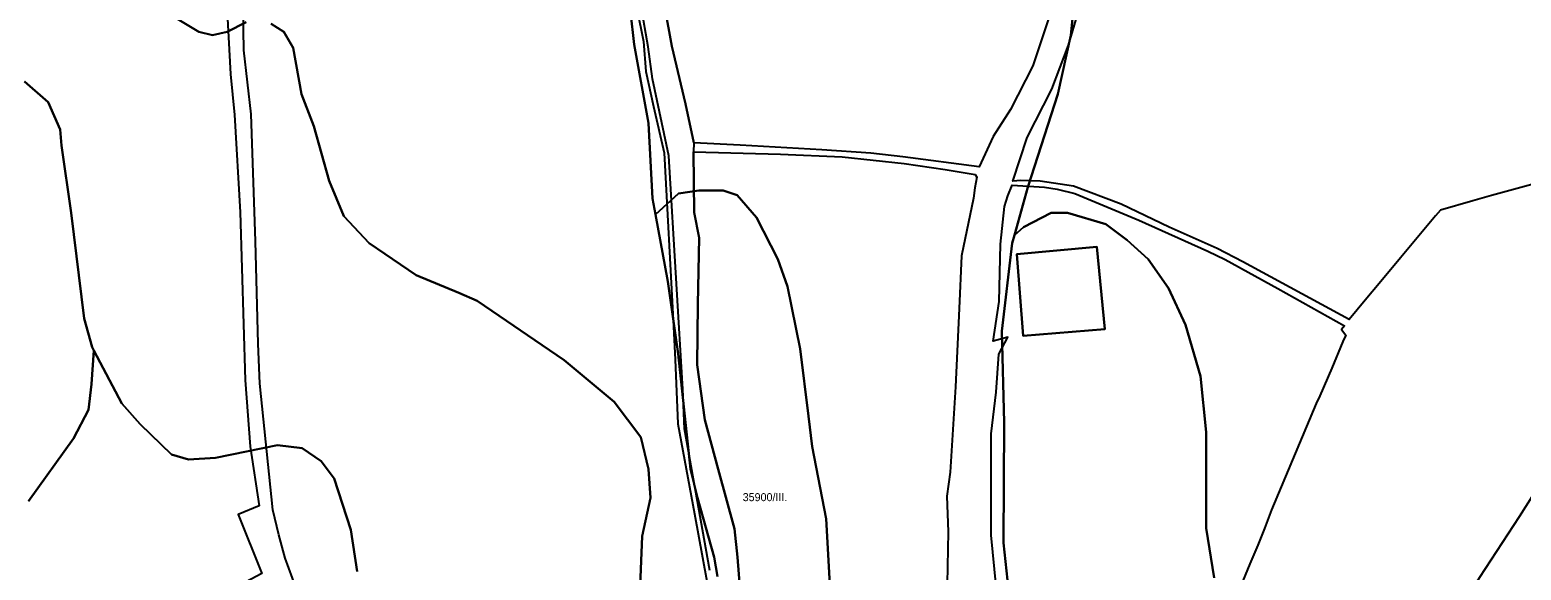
# Model space of a CAD drawing. Extents: x -532083 to -529270, y -1180561 to -1176456.
# Drawn here: x -531139 to -530208, y -1177679 to -1177342 of the extents above; entities that cross this region are included whole.
import ezdxf

# ---------------------------------------------------------------- set-up
doc = ezdxf.new("R2010")
doc.units = 0
for name, color, linetype in [('95560013', 7, 'Continuous'), ('95610013', 7, 'Continuous'), ('95660013', 7, 'Continuous')]:
    doc.layers.add(name, color=color, linetype=linetype)

msp = doc.modelspace()

# ---------------------------------------------------------------- linework, layer by layer
at = {"layer": '95560013'}
for points in [[(-530972.9683, -1177690.35345), (-530979.8183, -1177671.66545), (-530983.9283, -1177657.09845), (-530987.4903, -1177641.43345), (-530995.7103, -1177562.55645), (-530996.6723, -1177537.90445), (-530998.3133, -1177473.68045), (-531001.1283, -1177394.47345), (-531005.7623, -1177354.41745), (-531006.6203, -1177303.21945)], [(-530497.9153, -1177319.13345), (-530512.7543, -1177364.23845), (-530526.8243, -1177391.53445), (-530537.6733, -1177408.35145), (-530546.3023, -1177427.39445), (-530594.1343, -1177420.96445), (-530614.1053, -1177418.73845), (-530644.6773, -1177416.76045), (-530695.5913, -1177413.83345), (-530724.5473, -1177412.26945), (-530729.8643, -1177388.03045), (-530738.3213, -1177351.91345), (-530742.6713, -1177327.91645)], [(-530163.0193, -1177427.87145), (-530226.4153, -1177445.25745), (-530238.0503, -1177448.59145), (-530258.2323, -1177454.30845), (-530261.3193, -1177457.88045), (-530283.1633, -1177484.07945), (-530295.5103, -1177498.84545), (-530305.2453, -1177510.51545), (-530315.2923, -1177522.64845), (-530381.6713, -1177486.67145), (-530397.7303, -1177478.34845), (-530427.7073, -1177464.92445), (-530457.6853, -1177450.69545), (-530487.3953, -1177439.41945), (-530508.2723, -1177436.19745), (-530520.3163, -1177435.92845), (-530525.2543, -1177436.31745), (-530516.3373, -1177408.95945), (-530500.8653, -1177378.70845), (-530490.6373, -1177351.35145), (-530481.9833, -1177322.15245)], [(-531016.1163, -1177330.85845), (-531013.9583, -1177369.33145), (-531011.5613, -1177394.82245), (-531007.9653, -1177455.65945), (-531004.8483, -1177560.50445), (-531001.7323, -1177601.86645), (-530996.1843, -1177639.00245), (-531009.2363, -1177644.47345), (-530994.4313, -1177681.21145), (-531066.9013, -1177719.70745), (-531091.9053, -1177732.76545), (-531118.2913, -1177744.82245), (-531146.1423, -1177755.99745)], [(-530760.1993, -1177328.34445), (-530756.1083, -1177349.07945), (-530754.6013, -1177367.86945), (-530749.8703, -1177389.65445), (-530743.1753, -1177418.50645), (-530737.4993, -1177523.03345), (-530736.1873, -1177547.59845), (-530734.6563, -1177587.73645), (-530724.2453, -1177644.04445), (-530711.3873, -1177713.36945)], [(-530714.6403, -1177679.39445), (-530730.3473, -1177590.91845), (-530731.5553, -1177566.19345), (-530735.4223, -1177500.26045), (-530740.2553, -1177420.51045), (-530750.4043, -1177372.27445), (-530753.0623, -1177352.39845), (-530757.4123, -1177327.43145)], [(-530742.6713, -1177327.91645), (-530738.3213, -1177351.91345), (-530729.8643, -1177388.03045), (-530724.5473, -1177412.26945), (-530724.7193, -1177417.95145), (-530724.4793, -1177455.74945), (-530721.3593, -1177471.63845), (-530722.0793, -1177513.04645), (-530722.6183, -1177551.01945), (-530717.7763, -1177585.23745), (-530709.4133, -1177616.14445), (-530699.2893, -1177653.23245), (-530697.4183, -1177670.94245), (-530695.2093, -1177697.53345)], [(-530695.2093, -1177697.53345), (-530697.4183, -1177670.94245), (-530699.2893, -1177653.23245), (-530709.4133, -1177616.14445), (-530717.7763, -1177585.23745), (-530722.6183, -1177551.01945), (-530722.0793, -1177513.04645), (-530721.3593, -1177471.63845), (-530724.4793, -1177455.74945), (-530724.7193, -1177417.95145), (-530670.5343, -1177419.41845), (-530631.8653, -1177420.97045), (-530593.1953, -1177425.31445), (-530567.5193, -1177429.03845), (-530548.9583, -1177432.14145), (-530547.7813, -1177433.82545), (-530549.0143, -1177440.50245), (-530549.8333, -1177446.93445), (-530557.3753, -1177482.82145), (-530558.9533, -1177515.79945), (-530561.0733, -1177564.70345), (-530564.5173, -1177617.85945), (-530566.6373, -1177633.00845), (-530565.7593, -1177655.31045), (-530566.2513, -1177687.61045)], [(-530534.7493, -1177699.73945), (-530538.8693, -1177657.20545), (-530538.9023, -1177594.00945), (-530535.6643, -1177568.02745), (-530534.0453, -1177544.21145), (-530528.3793, -1177533.65645), (-530537.6503, -1177536.16645), (-530533.7823, -1177511.33645), (-530533.0093, -1177475.64445), (-530530.5233, -1177452.12645), (-530528.5503, -1177445.44845), (-530525.8383, -1177438.77145), (-530505.5953, -1177439.95645), (-530497.5663, -1177441.29845), (-530486.5923, -1177443.98345), (-530446.7113, -1177460.62945), (-530403.6183, -1177479.95945), (-530392.6443, -1177485.06045), (-530359.7233, -1177503.31745), (-530318.2363, -1177526.67545), (-530320.0873, -1177528.96545), (-530317.4173, -1177532.31245), (-530319.0863, -1177536.32945), (-530326.0943, -1177553.06645), (-530333.5213, -1177570.34045), (-530335.8553, -1177575.02345), (-530363.7173, -1177641.40045), (-530368.1183, -1177653.17445), (-530372.2263, -1177663.47645), (-530377.2153, -1177675.24945), (-530381.6163, -1177685.84645)], [(-530202.5013, -1177886.43345), (-530280.6013, -1177914.22245), (-530299.8523, -1177901.09045), (-530283.3193, -1177875.02245), (-530332.0333, -1177842.15945), (-530288.9793, -1177773.56145), (-530233.5283, -1177683.50645), (-530208.8843, -1177645.54245), (-530157.0203, -1177563.79845)]]:
    msp.add_lwpolyline(points, dxfattribs=at)
msp.add_lwpolyline([(-530518.9233, -1177532.82145), (-530467.9253, -1177528.59545), (-530472.8033, -1177477.21845), (-530522.9143, -1177481.88945)], close=True, dxfattribs=at)
at = {"layer": '95610013'}
msp.add_lwpolyline([(-530467.9253, -1177528.59545), (-530518.9233, -1177532.82145), (-530522.9143, -1177481.88945), (-530472.8033, -1177477.21845)], close=True, dxfattribs=at)
at = {"layer": '95660013'}
for points in [[(-530485.1253, -1177306.00045), (-530489.1253, -1177345.00045), (-530497.3123, -1177382.00045), (-530515.8753, -1177440.00045), (-530524.3753, -1177470.00045), (-530525.8123, -1177475.00045), (-530532.1253, -1177530.00045), (-530530.8123, -1177587.00045), (-530531.1253, -1177662.00045), (-530527.5003, -1177697.00045)], [(-530399.6253, -1177684.00045), (-530404.6253, -1177653.00045), (-530404.6253, -1177593.00045), (-530408.1873, -1177558.00045), (-530417.3753, -1177526.00045), (-530428.1253, -1177503.00045), (-530440.6873, -1177485.00045), (-530453.8753, -1177473.00045), (-530467.1873, -1177463.00045), (-530491.1253, -1177456.00045), (-530501.3123, -1177456.00045), (-530518.6253, -1177465.00045), (-530524.3753, -1177470.00045), (-530515.8753, -1177440.00045), (-530497.3123, -1177382.00045), (-530489.1253, -1177345.00045), (-530485.1253, -1177306.00045)], [(-530766.3753, -1177310.00045), (-530761.8753, -1177351.00045), (-530753.0003, -1177400.00045), (-530750.3753, -1177447.00045), (-530748.5003, -1177457.00045), (-530740.8753, -1177499.00045), (-530734.3753, -1177544.00045), (-530726.6253, -1177616.00045), (-530722.3123, -1177634.00045), (-530711.8753, -1177671.00045), (-530709.8753, -1177683.00045)], [(-530639.6253, -1177688.00045), (-530641.8753, -1177647.00045), (-530650.6253, -1177602.00045), (-530652.8753, -1177583.00045), (-530658.1873, -1177541.00045), (-530666.1873, -1177502.00045), (-530672.1873, -1177485.00045), (-530685.5003, -1177459.00045), (-530697.5003, -1177445.00045), (-530706.1873, -1177442.00045), (-530721.5003, -1177442.00045), (-530734.1253, -1177444.00045), (-530748.5003, -1177457.00045), (-530750.3753, -1177447.00045), (-530753.0003, -1177400.00045), (-530761.8753, -1177351.00045), (-530766.3753, -1177310.00045)], [(-531004.3123, -1177337.00045), (-531016.1253, -1177343.00045), (-531025.3123, -1177345.00045), (-531033.8123, -1177343.00045), (-531050.3753, -1177333.00045)], [(-531050.3753, -1177333.00045), (-531033.8123, -1177343.00045), (-531025.3123, -1177345.00045), (-531016.1253, -1177343.00045), (-531004.3123, -1177337.00045)], [(-530758.3123, -1177694.00045), (-530756.8753, -1177658.00045), (-530751.6873, -1177634.00045), (-530753.0003, -1177616.00045), (-530757.6253, -1177596.00045), (-530774.3123, -1177574.00045), (-530805.6253, -1177548.00045), (-530859.8753, -1177511.00045), (-530871.3123, -1177506.00045), (-530898.1253, -1177495.00045), (-530927.5003, -1177475.00045), (-530943.1873, -1177458.00045), (-530952.3753, -1177436.00045), (-530961.8753, -1177402.00045), (-530969.6873, -1177382.00045), (-530974.8753, -1177353.00045), (-530980.8123, -1177343.00045), (-530988.6253, -1177338.00045)], [(-530988.6253, -1177338.00045), (-530980.8123, -1177343.00045), (-530974.8753, -1177353.00045), (-530969.6873, -1177382.00045), (-530961.8753, -1177402.00045), (-530952.3753, -1177436.00045), (-530943.1873, -1177458.00045), (-530927.5003, -1177475.00045), (-530898.1253, -1177495.00045), (-530871.3123, -1177506.00045), (-530859.8753, -1177511.00045), (-530805.6253, -1177548.00045), (-530774.3123, -1177574.00045), (-530757.6253, -1177596.00045), (-530753.0003, -1177616.00045), (-530751.6873, -1177634.00045), (-530756.8753, -1177658.00045), (-530758.3123, -1177694.00045)], [(-531142.6253, -1177374.00045), (-531127.8753, -1177387.00045), (-531120.5003, -1177404.00045), (-531119.5003, -1177414.00045), (-531113.5003, -1177456.00045), (-531105.5003, -1177522.00045), (-531100.3753, -1177540.00045), (-531099.3123, -1177542.00045), (-531100.8123, -1177563.00045), (-531102.8123, -1177579.00045), (-531112.1873, -1177597.00045), (-531140.3123, -1177636.00045)], [(-530934.8123, -1177680.00045), (-530938.8753, -1177654.00045), (-530949.3123, -1177622.00045), (-530957.3123, -1177611.00045), (-530969.3123, -1177603.00045), (-530984.6873, -1177601.00045), (-531023.5003, -1177609.00045), (-531040.3123, -1177610.00045), (-531050.8753, -1177607.00045), (-531070.3753, -1177588.00045), (-531081.8123, -1177575.00045), (-531099.3123, -1177542.00045), (-531100.3753, -1177540.00045), (-531105.5003, -1177522.00045), (-531113.5003, -1177456.00045), (-531119.5003, -1177414.00045), (-531120.5003, -1177404.00045), (-531127.8753, -1177387.00045), (-531142.6253, -1177374.00045)], [(-530709.8753, -1177683.00045), (-530711.8753, -1177671.00045), (-530722.3123, -1177634.00045), (-530726.6253, -1177616.00045), (-530734.3753, -1177544.00045), (-530740.8753, -1177499.00045), (-530748.5003, -1177457.00045), (-530734.1253, -1177444.00045), (-530721.5003, -1177442.00045), (-530706.1873, -1177442.00045), (-530697.5003, -1177445.00045), (-530685.5003, -1177459.00045), (-530672.1873, -1177485.00045), (-530666.1873, -1177502.00045), (-530658.1873, -1177541.00045), (-530652.8753, -1177583.00045), (-530650.6253, -1177602.00045), (-530641.8753, -1177647.00045), (-530639.6253, -1177688.00045)], [(-530527.5003, -1177697.00045), (-530531.1253, -1177662.00045), (-530530.8123, -1177587.00045), (-530532.1253, -1177530.00045), (-530525.8123, -1177475.00045), (-530524.3753, -1177470.00045), (-530518.6253, -1177465.00045), (-530501.3123, -1177456.00045), (-530491.1253, -1177456.00045), (-530467.1873, -1177463.00045), (-530453.8753, -1177473.00045), (-530440.6873, -1177485.00045), (-530428.1253, -1177503.00045), (-530417.3753, -1177526.00045), (-530408.1873, -1177558.00045), (-530404.6253, -1177593.00045), (-530404.6253, -1177653.00045), (-530399.6253, -1177684.00045)], [(-531140.3123, -1177636.00045), (-531112.1873, -1177597.00045), (-531102.8123, -1177579.00045), (-531100.8123, -1177563.00045), (-531099.3123, -1177542.00045), (-531081.8123, -1177575.00045), (-531070.3753, -1177588.00045), (-531050.8753, -1177607.00045), (-531040.3123, -1177610.00045), (-531023.5003, -1177609.00045), (-530984.6873, -1177601.00045), (-530969.3123, -1177603.00045), (-530957.3123, -1177611.00045), (-530949.3123, -1177622.00045), (-530938.8753, -1177654.00045), (-530934.8123, -1177680.00045)]]:
    msp.add_lwpolyline(points, dxfattribs=at)

# ---------------------------------------------------------------- texts
msp.add_text('35900/III.', height=5, rotation=0.00000004, dxfattribs=at).set_placement((-530694.0628, -1177636.05938))

doc.saveas('drawing.dxf')
